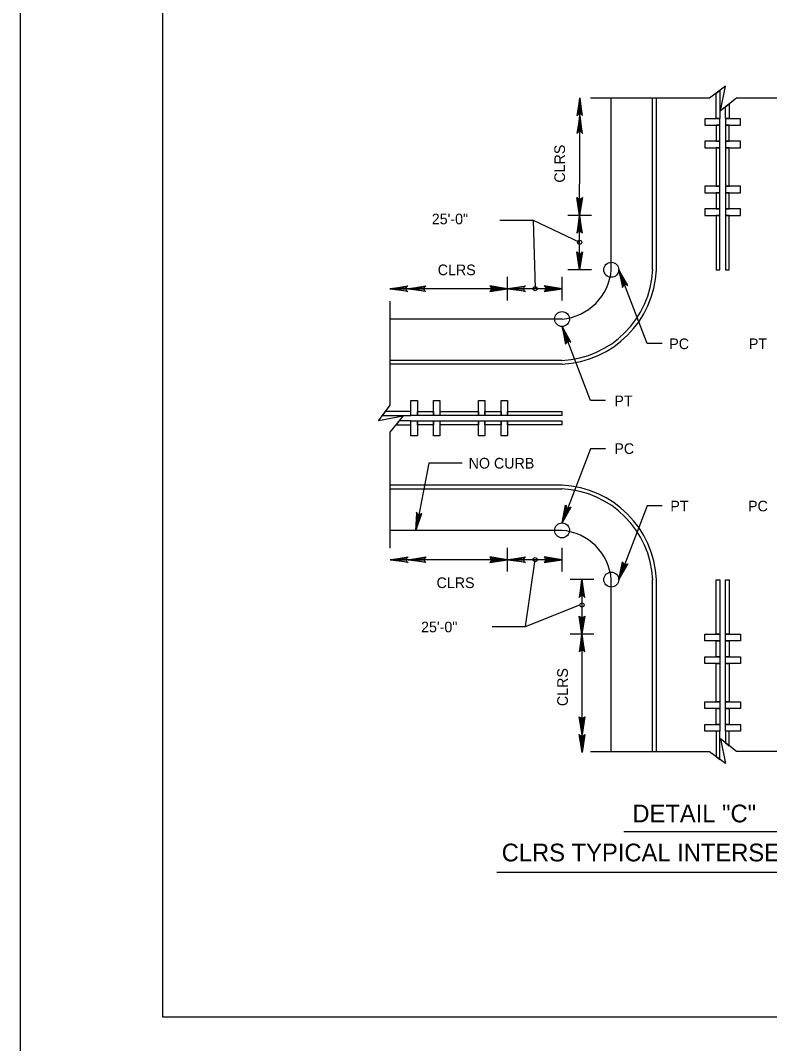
# Model space of a CAD drawing. Extents: x 632008 to 634206, y 294231 to 297795.
# Drawn here: x 632007.9 to 632218.9, y 297208.1 to 297496.3 of the extents above; entities that cross this region are included whole.
import ezdxf

# ---------------------------------------------------------------- set-up
doc = ezdxf.new("R2010")
doc.units = 0
for name, color, linetype in [('1', 7, 'Continuous'), ('3', 7, 'Continuous'), ('Level 2', 7, 'Continuous'), ('PLT-BNDY', 7, 'Continuous')]:
    doc.layers.add(name, color=color, linetype=linetype)

msp = doc.modelspace()

# ---------------------------------------------------------------- linework, layer by layer
at = {"layer": '1'}
for p, q in [((632177.83, 297267.85), (632230.42, 297267.85)), ((632142.03, 297256.38), (632268.98, 297256.38))]:
    msp.add_line(p, q, dxfattribs=at)
msp.add_lwpolyline([(632833.86, 297215.62), (632833.86, 297779.62), (632047.86, 297779.62), (632047.86, 297215.62), (632833.86, 297215.62), (632833.86, 297241.98), (632633.86, 297241.98), (632633.86, 297306.66), (632833.86, 297306.66), (632833.86, 297335.62), (632633.86, 297335.62), (632633.86, 297215.62), (632712.66, 297215.62), (632712.66, 297241.98), (632712.66, 297215.62), (632789.66, 297215.62), (632789.66, 297241.98), (632789.66, 297229.66), (632833.86, 297229.66)], dxfattribs=at)
for points in [[(632203.81, 297468.66), (632203.81, 297475.83), (632204.87, 297476.63), (632204.87, 297468.66)], [(632206.45, 297468.66), (632206.45, 297471.95), (632207.51, 297472.8), (632207.51, 297468.66)], [(632203.81, 297466.8), (632203.81, 297462.29), (632204.87, 297462.29), (632204.87, 297466.8)], [(632206.45, 297466.8), (632206.45, 297462.29), (632207.51, 297462.29), (632207.51, 297466.8)], [(632203.81, 297460.4), (632203.81, 297449.62), (632204.87, 297449.62), (632204.87, 297460.4)], [(632206.45, 297460.4), (632206.45, 297449.62), (632207.51, 297449.62), (632207.51, 297460.4)], [(632203.81, 297447.78), (632203.81, 297443.24), (632204.87, 297443.24), (632204.87, 297447.78)], [(632206.45, 297447.78), (632206.45, 297443.24), (632207.51, 297443.24), (632207.51, 297447.78)], [(632203.81, 297441.39), (632203.81, 297426.07), (632204.87, 297426.07), (632204.87, 297441.39)], [(632206.45, 297441.39), (632206.45, 297426.07), (632207.51, 297426.07), (632207.51, 297441.39)], [(632117.8, 297386.14), (632110.63, 297386.14), (632109.83, 297385.08), (632117.8, 297385.08)], [(632119.66, 297386.14), (632124.18, 297386.14), (632124.18, 297385.08), (632119.66, 297385.08)], [(632126.06, 297386.14), (632136.84, 297386.14), (632136.84, 297385.08), (632126.06, 297385.08)], [(632138.69, 297386.14), (632143.23, 297386.14), (632143.23, 297385.08), (632138.69, 297385.08)], [(632145.07, 297386.14), (632160.39, 297386.14), (632160.39, 297385.08), (632145.07, 297385.08)], [(632117.8, 297383.5), (632114.51, 297383.5), (632113.66, 297382.44), (632117.8, 297382.44)], [(632119.66, 297383.5), (632124.18, 297383.5), (632124.18, 297382.44), (632119.66, 297382.44)], [(632126.06, 297383.5), (632136.84, 297383.5), (632136.84, 297382.44), (632126.06, 297382.44)], [(632138.69, 297383.5), (632143.23, 297383.5), (632143.23, 297382.44), (632138.69, 297382.44)], [(632145.07, 297383.5), (632160.39, 297383.5), (632160.39, 297382.44), (632145.07, 297382.44)], [(632203.81, 297323.42), (632203.81, 297338.73), (632204.87, 297338.73), (632204.87, 297323.42)], [(632206.45, 297323.42), (632206.45, 297338.73), (632207.51, 297338.73), (632207.51, 297323.42)], [(632203.81, 297317.03), (632203.81, 297321.57), (632204.87, 297321.57), (632204.87, 297317.03)], [(632206.45, 297317.03), (632206.45, 297321.57), (632207.51, 297321.57), (632207.51, 297317.03)], [(632203.81, 297304.4), (632203.81, 297315.18), (632204.87, 297315.18), (632204.87, 297304.4)], [(632206.45, 297304.4), (632206.45, 297315.18), (632207.51, 297315.18), (632207.51, 297304.4)], [(632203.81, 297298), (632203.81, 297302.52), (632204.87, 297302.52), (632204.87, 297298)], [(632206.45, 297298), (632206.45, 297302.52), (632207.51, 297302.52), (632207.51, 297298)], [(632203.81, 297296.14), (632203.81, 297288.97), (632204.87, 297288.17), (632204.87, 297296.14)], [(632206.45, 297296.14), (632206.45, 297292.86), (632207.51, 297292), (632207.51, 297296.14)]]:
    msp.add_lwpolyline(points, close=True, dxfattribs=at)
at = {"layer": '3'}
for p, q in [((632165.35, 297426.08), (632165.4, 297474.55)), ((632152.31, 297440.09), (632165.36, 297433.84)), ((632168.66, 297441.42), (632162.05, 297441.42)), ((632168.66, 297426.08), (632162.05, 297426.08)), ((632145.07, 297417.46), (632145.07, 297424.07)), ((632160.41, 297417.46), (632160.41, 297424.07)), ((632160.41, 297420.76), (632111.92, 297420.74)), ((632145.07, 297341.11), (632145.07, 297347.72)), ((632160.41, 297341.11), (632160.41, 297347.72)), ((632160.41, 297344.41), (632112.01, 297344.41)), ((632150.1, 297325.57), (632152.86, 297344.44)), ((632169.33, 297338.81), (632162.72, 297338.81)), ((632166.02, 297338.81), (632166.02, 297290.33)), ((632169.33, 297323.48), (632162.72, 297323.48))]:
    msp.add_line(p, q, dxfattribs=at)
for points in [[(632166, 297469.75), (632165.66, 297469.93), (632165.4, 297474.55), (632166, 297469.75), (632166.21, 297469.51), (632165.4, 297474.55), (632165.17, 297469.93), (632164.83, 297469.76), (632165.4, 297474.55), (632164.6, 297469.51), (632164.83, 297469.76)], [(632166, 297464.73), (632165.66, 297464.91), (632165.4, 297469.53), (632166, 297464.73), (632166.21, 297464.49), (632165.4, 297469.53), (632165.17, 297464.91), (632164.83, 297464.74), (632165.4, 297469.53), (632164.6, 297464.49), (632164.83, 297464.74)], [(632165.97, 297446.22), (632165.63, 297446.04), (632165.37, 297441.42), (632165.97, 297446.22), (632166.18, 297446.46), (632165.37, 297441.42), (632165.14, 297446.03), (632164.8, 297446.2), (632165.37, 297441.42), (632164.57, 297446.46), (632164.8, 297446.2)], [(632142.9, 297440.09), (632152.31, 297440.09), (632152.83, 297420.78)], [(632165.96, 297436.63), (632165.61, 297436.8), (632165.35, 297441.42), (632165.96, 297436.63), (632166.16, 297436.38), (632165.35, 297441.42), (632165.12, 297436.81), (632164.78, 297436.64), (632165.35, 297441.42), (632164.55, 297436.38), (632164.78, 297436.64)], [(632165.96, 297430.88), (632165.61, 297430.7), (632165.35, 297426.08), (632165.96, 297430.88), (632166.16, 297431.12), (632165.35, 297426.08), (632165.12, 297430.7), (632164.78, 297430.86), (632165.35, 297426.08), (632164.55, 297431.12), (632164.78, 297430.86)], [(632188.6, 297405.27), (632184.38, 297405.27), (632176.39, 297426.08)], [(632178.63, 297421.8), (632178.24, 297421.84), (632176.39, 297426.08), (632178.63, 297421.8), (632178.91, 297421.64), (632176.39, 297426.08), (632177.78, 297421.68), (632177.52, 297421.4), (632176.39, 297426.08), (632177.4, 297421.08), (632177.52, 297421.4)], [(632116.71, 297420.14), (632116.54, 297420.49), (632111.92, 297420.74), (632116.71, 297420.14), (632116.96, 297419.93), (632111.92, 297420.74), (632116.53, 297420.97), (632116.7, 297421.31), (632111.92, 297420.74), (632116.96, 297421.54), (632116.7, 297421.31)], [(632121.73, 297420.14), (632121.56, 297420.49), (632116.94, 297420.74), (632121.73, 297420.14), (632121.98, 297419.93), (632116.94, 297420.74), (632121.55, 297420.97), (632121.72, 297421.31), (632116.94, 297420.74), (632121.98, 297421.54), (632121.72, 297421.31)], [(632140.28, 297420.16), (632140.45, 297420.5), (632145.07, 297420.76), (632140.28, 297420.16), (632140.03, 297419.95), (632145.07, 297420.76), (632140.46, 297420.99), (632140.29, 297421.33), (632145.07, 297420.76), (632140.03, 297421.56), (632140.29, 297421.33)], [(632149.87, 297420.16), (632149.69, 297420.5), (632145.07, 297420.76), (632149.87, 297420.16), (632150.11, 297419.95), (632145.07, 297420.76), (632149.68, 297420.99), (632149.85, 297421.33), (632145.07, 297420.76), (632150.11, 297421.56), (632149.85, 297421.33)], [(632155.62, 297420.16), (632155.79, 297420.5), (632160.41, 297420.76), (632155.62, 297420.16), (632155.37, 297419.95), (632160.41, 297420.76), (632155.8, 297420.99), (632155.63, 297421.33), (632160.41, 297420.76), (632155.37, 297421.56), (632155.63, 297421.33)], [(632162.65, 297405.82), (632162.26, 297405.86), (632160.41, 297410.1), (632162.65, 297405.82), (632162.93, 297405.66), (632160.41, 297410.1), (632161.8, 297405.7), (632161.54, 297405.42), (632160.41, 297410.1), (632161.42, 297405.1), (632161.54, 297405.42)], [(632172.62, 297389.29), (632168.4, 297389.29), (632160.41, 297410.1)], [(632172.62, 297375.6), (632168.4, 297375.6), (632160.41, 297354.79)], [(632132.29, 297371.57), (632122.88, 297371.57), (632119.18, 297352.68)], [(632162.65, 297359.08), (632162.26, 297359.03), (632160.41, 297354.79), (632162.65, 297359.08), (632162.93, 297359.23), (632160.41, 297354.79), (632161.8, 297359.2), (632161.54, 297359.47), (632160.41, 297354.79), (632161.42, 297359.8), (632161.54, 297359.47)], [(632188.6, 297359.62), (632184.38, 297359.62), (632176.39, 297338.81)], [(632119.53, 297357.5), (632119.83, 297357.26), (632119.18, 297352.68), (632119.53, 297357.5), (632119.37, 297357.79), (632119.18, 297352.68), (632120.31, 297357.16), (632120.67, 297357.26), (632119.18, 297352.68), (632120.95, 297357.47), (632120.67, 297357.26)], [(632116.81, 297343.81), (632116.63, 297344.16), (632112.01, 297344.41), (632116.81, 297343.81), (632117.05, 297343.6), (632112.01, 297344.41), (632116.62, 297344.64), (632116.79, 297344.98), (632112.01, 297344.41), (632117.05, 297345.21), (632116.79, 297344.98)], [(632121.83, 297343.81), (632121.65, 297344.16), (632117.03, 297344.41), (632121.83, 297343.81), (632122.07, 297343.6), (632117.03, 297344.41), (632121.65, 297344.64), (632121.81, 297344.98), (632117.03, 297344.41), (632122.07, 297345.21), (632121.81, 297344.98)], [(632140.28, 297343.81), (632140.45, 297344.16), (632145.07, 297344.41), (632140.28, 297343.81), (632140.03, 297343.6), (632145.07, 297344.41), (632140.46, 297344.64), (632140.29, 297344.98), (632145.07, 297344.41), (632140.03, 297345.21), (632140.29, 297344.98)], [(632149.87, 297343.81), (632149.69, 297344.16), (632145.07, 297344.41), (632149.87, 297343.81), (632150.11, 297343.6), (632145.07, 297344.41), (632149.68, 297344.64), (632149.85, 297344.98), (632145.07, 297344.41), (632150.11, 297345.21), (632149.85, 297344.98)], [(632155.62, 297343.81), (632155.79, 297344.16), (632160.41, 297344.41), (632155.62, 297343.81), (632155.37, 297343.6), (632160.41, 297344.41), (632155.8, 297344.64), (632155.63, 297344.98), (632160.41, 297344.41), (632155.37, 297345.21), (632155.63, 297344.98)], [(632178.63, 297343.1), (632178.24, 297343.05), (632176.39, 297338.81), (632178.63, 297343.1), (632178.91, 297343.25), (632176.39, 297338.81), (632177.78, 297343.22), (632177.52, 297343.49), (632176.39, 297338.81), (632177.4, 297343.82), (632177.52, 297343.49)], [(632166.63, 297334.02), (632166.28, 297334.19), (632166.02, 297338.81), (632166.63, 297334.02), (632166.83, 297333.77), (632166.02, 297338.81), (632165.79, 297334.2), (632165.45, 297334.03), (632166.02, 297338.81), (632165.22, 297333.77), (632165.45, 297334.03)], [(632140.68, 297325.57), (632150.1, 297325.57), (632165.46, 297331.66)], [(632166.63, 297328.27), (632166.28, 297328.09), (632166.02, 297323.48), (632166.63, 297328.27), (632166.83, 297328.52), (632166.02, 297323.48), (632165.79, 297328.09), (632165.45, 297328.26), (632166.02, 297323.48), (632165.22, 297328.52), (632165.45, 297328.26)], [(632166.63, 297318.68), (632166.28, 297318.86), (632166.02, 297323.48), (632166.63, 297318.68), (632166.83, 297318.43), (632166.02, 297323.48), (632165.79, 297318.86), (632165.45, 297318.69), (632166.02, 297323.48), (632165.22, 297318.43), (632165.45, 297318.69)], [(632166.63, 297299.94), (632166.28, 297299.76), (632166.03, 297295.14), (632166.63, 297299.94), (632166.84, 297300.18), (632166.03, 297295.14), (632165.8, 297299.76), (632165.46, 297299.92), (632166.03, 297295.14), (632165.23, 297300.18), (632165.46, 297299.92)], [(632166.63, 297294.92), (632166.28, 297294.74), (632166.03, 297290.12), (632166.63, 297294.92), (632166.84, 297295.16), (632166.03, 297290.12), (632165.8, 297294.73), (632165.46, 297294.9), (632166.03, 297290.12), (632165.23, 297295.16), (632165.46, 297294.9)]]:
    msp.add_lwpolyline(points, dxfattribs=at)
for centre, radius in [((632165.36, 297433.84), 0.581), ((632174.28, 297426.08), 2.11), ((632152.83, 297420.78), 0.581), ((632160.41, 297412.21), 2.11), ((632160.41, 297352.68), 2.11), ((632152.83, 297344.41), 0.581), ((632174.28, 297338.81), 2.11), ((632166.03, 297331.68), 0.581)]:
    msp.add_circle(centre, radius, dxfattribs=at)
at = {"layer": 'Level 2'}
for p, q in [((632206.41, 297477.79), (632201.98, 297474.47)), ((632205.06, 297470.82), (632206.41, 297477.79)), ((632201.98, 297474.47), (632168.38, 297474.47)), ((632174.28, 297426.08), (632174.28, 297474.47)), ((632185.93, 297426.08), (632185.93, 297474.47)), ((632186.98, 297426.08), (632186.98, 297474.47)), ((632209.56, 297474.47), (632205.06, 297470.82)), ((632239.55, 297474.47), (632209.56, 297474.47)), ((632111.99, 297387.97), (632111.99, 297417.26)), ((632160.41, 297412.21), (632111.99, 297412.21)), ((632160.41, 297400.56), (632111.99, 297400.56)), ((632160.41, 297399.51), (632111.99, 297399.51)), ((632108.67, 297383.54), (632111.99, 297387.97)), ((632115.64, 297384.89), (632108.67, 297383.54)), ((632111.99, 297380.38), (632115.64, 297384.89)), ((632111.99, 297347.63), (632111.99, 297380.38)), ((632160.41, 297365.39), (632111.99, 297365.39)), ((632160.41, 297364.33), (632111.99, 297364.33)), ((632160.41, 297352.68), (632111.99, 297352.68)), ((632174.28, 297290.33), (632174.28, 297338.81)), ((632185.93, 297290.33), (632185.93, 297338.81)), ((632186.98, 297290.33), (632186.98, 297338.81)), ((632209.56, 297290.34), (632205.06, 297293.98)), ((632205.06, 297293.98), (632206.41, 297287.01)), ((632201.98, 297290.33), (632168.38, 297290.33)), ((632206.41, 297287.01), (632201.98, 297290.33)), ((632239.55, 297290.34), (632209.56, 297290.34))]:
    msp.add_line(p, q, dxfattribs=at)
for points in [[(632204.87, 297466.8), (632204.87, 297468.65), (632200.65, 297468.65), (632200.65, 297466.8)], [(632210.67, 297466.8), (632210.67, 297468.65), (632206.45, 297468.65), (632206.45, 297466.8)], [(632204.87, 297460.44), (632204.87, 297462.29), (632200.65, 297462.29), (632200.65, 297460.44)], [(632210.67, 297460.44), (632210.67, 297462.29), (632206.45, 297462.29), (632206.45, 297460.44)], [(632204.87, 297447.78), (632204.87, 297449.62), (632200.65, 297449.62), (632200.65, 297447.78)], [(632210.67, 297447.78), (632210.67, 297449.62), (632206.45, 297449.62), (632206.45, 297447.78)], [(632204.87, 297441.39), (632204.87, 297443.24), (632200.64, 297443.24), (632200.64, 297441.39)], [(632210.67, 297441.39), (632210.67, 297443.24), (632206.45, 297443.24), (632206.45, 297441.39)], [(632119.66, 297385.08), (632117.81, 297385.08), (632117.81, 297389.3), (632119.66, 297389.3)], [(632126.02, 297385.08), (632124.18, 297385.08), (632124.18, 297389.3), (632126.02, 297389.3)], [(632138.69, 297385.08), (632136.84, 297385.08), (632136.84, 297389.3), (632138.69, 297389.3)], [(632145.07, 297385.08), (632143.23, 297385.08), (632143.23, 297389.3), (632145.07, 297389.3)], [(632119.66, 297379.27), (632117.81, 297379.27), (632117.81, 297383.5), (632119.66, 297383.5)], [(632126.02, 297379.27), (632124.18, 297379.27), (632124.18, 297383.5), (632126.02, 297383.5)], [(632138.69, 297379.27), (632136.84, 297379.27), (632136.84, 297383.5), (632138.69, 297383.5)], [(632145.07, 297379.27), (632143.23, 297379.27), (632143.23, 297383.5), (632145.07, 297383.5)], [(632204.87, 297323.42), (632204.87, 297321.57), (632200.64, 297321.57), (632200.64, 297323.42)], [(632210.67, 297323.42), (632210.67, 297321.57), (632206.45, 297321.57), (632206.45, 297323.42)], [(632204.87, 297317.03), (632204.87, 297315.18), (632200.65, 297315.18), (632200.65, 297317.03)], [(632210.67, 297317.03), (632210.67, 297315.18), (632206.45, 297315.18), (632206.45, 297317.03)], [(632204.87, 297304.37), (632204.87, 297302.52), (632200.65, 297302.52), (632200.65, 297304.37)], [(632210.67, 297304.37), (632210.67, 297302.52), (632206.45, 297302.52), (632206.45, 297304.37)], [(632204.87, 297298), (632204.87, 297296.15), (632200.65, 297296.15), (632200.65, 297298)], [(632210.67, 297298), (632210.67, 297296.15), (632206.45, 297296.15), (632206.45, 297298)]]:
    msp.add_lwpolyline(points, close=True, dxfattribs=at)
for centre, radius, start, end in [((632159.13, 297427.37), 26.86, 272.6354, 357.3646), ((632159.13, 297427.37), 15.21, 274.837, 355.163), ((632159.13, 297427.37), 27.91, 272.6354, 357.3646), ((632159.13, 297337.53), 27.91, 2.6354, 87.3646), ((632159.13, 297337.53), 26.86, 2.6354, 87.3646), ((632159.13, 297337.53), 15.21, 4.837, 85.163)]:
    msp.add_arc(centre, radius, start, end, dxfattribs=at)
at = {"layer": 'PLT-BNDY'}
msp.add_lwpolyline([(632007.86, 297794.62), (632848.86, 297794.62), (632848.86, 297200.62), (632007.86, 297200.62)], close=True, dxfattribs=at)

# ---------------------------------------------------------------- texts
at = {"layer": '3'}
for p in [(632161.24, 297450.63), (632162.05, 297303.17)]:
    msp.add_text('CLRS', height=3, rotation=90, dxfattribs=at).set_placement(p)
for s, p in [('25\'-0"', (632123.72, 297438.89)), ('CLRS', (632125.39, 297424.56)), ('PC', (632190.61, 297403.73)), ('PT', (632213.04, 297403.73)), ('PT', (632175.14, 297387.66)), ('PC', (632175.14, 297374.2)), ('NO CURB', (632134.1, 297370.09)), ('PT', (632190.91, 297358.03)), ('PC', (632212.8, 297358.03)), ('CLRS', (632125.06, 297336.43)), ('25\'-0"', (632120.7, 297323.96))]:
    msp.add_text(s, height=3, dxfattribs=at).set_placement(p)
at = {"layer": 'Level 2'}
for s, p in [('DETAIL "C"', (632180.22, 297270.43)), ('CLRS TYPICAL INTERSECTION', (632143.41, 297259.43))]:
    msp.add_text(s, height=5, dxfattribs=at).set_placement(p)

doc.saveas('drawing.dxf')
